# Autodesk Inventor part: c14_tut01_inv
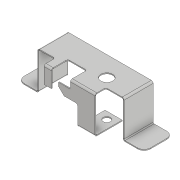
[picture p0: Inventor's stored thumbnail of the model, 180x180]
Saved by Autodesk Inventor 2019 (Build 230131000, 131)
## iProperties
Created: 2015-06
Part Number: c14_tut01_inv
Material: Generic
Document SubType Name: Sheet Metal
Designer: Sandeep
Density: 1 g/cm^3
Sheet Metal Rule: Default_mm
Appearance: Default
Flat Pattern Width: 11.1524 cm
Flat Pattern Length: 21.7129 cm
Flat Pattern Area: 242.15 cm^2
Sheet Metal Width: 111.524 mm
Sheet Metal Length: 217.129 mm
Sheet Metal Area: 24215.030 mm^2
Author: Sandeep
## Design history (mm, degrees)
node "Face1"
  sketch "Sketch1"
    geometry: L1 (0, 12)-(0, 44); L2 (0, 44)-(95, 44); L3 (95, 44)-(95, 12); L4 (95, 12)-(75, 12); L5 (75, 12)-(75, 0); L6 (75, 0)-(48, 0); L7 (48, 0)-(48, 18); L8 (48, 18)-(27, 18); L9 (27, 18)-(27, 0); L10 (27, 0)-(19, 0); L11 (19, 0)-(19, 12); L12 (19, 12)-(0, 12); L13 (0, 0)-(0, 88.508); L14 (0, 0)-(152.255, 0)
    constraints: 28 end point, 11 perpendicular, 4 point on line, 2 vertical, 1 horizontal
    dimensions: "d0" = 26 distance between parallel lines of L2 L8; "d1" = 19 distance between parallel lines of L13 L11; "d2" = 8 distance between parallel lines of L9 L11; "d3" = 32 distance between parallel lines of L12 L2; "d4" = 27 distance between parallel lines of L5 L7; "d5" = 20 distance between parallel lines of L3 L5; "d6" = 95 distance between parallel lines of L1 L3; "d7" = 44 distance between parallel lines of L6 L2
node "Contour Flange1"
node "Contour Flange3"
  sketch "Sketch10"
    geometry: L1 (0, 0)-(41, 0); L2 (41, 0)-(41, 30)
    constraints: 4 end point, 1 horizontal, 1 perpendicular
    dimensions: "d42" = 41 distance of L1.start L1.end; "d43" = 30 distance of L1.end L2.end
sketch "Sketch11"
  geometry: L1 (-3.447, 20)-(8, 20); L2 (8, 20)-(8, -8.777); L3 (8, -8.777)-(-3.447, -8.777); L4 (-3.447, -8.777)-(-3.447, 20); L5 (27, 37)-(27, 0) reference; L6 (0, 39)-(-21, 39) reference; 1 further point
  constraints: 8 end point, 2 parallel, 1 horizontal, 1 perpendicular
  dimensions: "d45" = 19 distance between parallel lines of L5 L2; "d104" = 19 distance between parallel lines of L6 L1
cut "Cut1" sketch "Sketch11" dims "d46" = 1 (= Thickness), "d47" = 0
node "Face2"
  sketch "Sketch12"
    geometry: L1 (0, -17)-(-13, -17); L2 (-13, -17)-(-13, -7); L3 (-13, -7)-(0, -7); L4 (0, 0)-(0, -17) reference; 1 further point
    constraints: 6 end point, 2 perpendicular, 1 horizontal, 1 point on line
    dimensions: "d54" = 13 distance between parallel lines of L2 L4; "d55" = 10 distance of L1.end L2.end
feature "Corner Round1" dims "d56" = 2
feature "Corner Chamfer1" dims "d57" = 6, "d58" = 6, angle "d59" = 45 deg
node "Flange1"
hole "Hole1" diameter "d72" = 13; stored, may be unused: countersink angle "d76" = 90 deg, drill point angle "d78" = 0 deg; dims "d70" = 9, "d71" = 22, "d73" = 6, "d74" = 4, "d75" = 2, "d77" = 1 (= Thickness)
hole "Hole2" diameter "d81" = 8; stored, may be unused: countersink angle "d85" = 90 deg, drill point angle "d87" = 0 deg; dims "d79" = 9, "d80" = 22, "d82" = 6, "d83" = 4, "d84" = 2, "d86" = 1 (= Thickness)
feature "Corner Round2" dims "d88" = 7
workplane "Work Plane1"
node "Contour Flange4"
  sketch "Sketch15"
    geometry: L1 (0, 0.919)-(0, -40.081); L2 (0, -40.081)-(-22, -40.081); 1 further point
    constraints: 4 end point, 1 perpendicular, 1 vertical
    dimensions: "d90" = 41 distance of L1.start L1.end; "d91" = 22 distance of L1.end L2.end
feature "Corner Round4" dims "d101" = 7
feature "Corner Round5" dims "d102" = 2
body "Solid1"
face "Plate1" dims "d103" = 1 (= Thickness)
sketch "Sketch6"
  geometry: L1 (-75, 1)-(20, 1) reference; L2 (20, 1)-(20, -39); L3 (20, -39)-(42, -39); L4 (-75, 1)-(-75, -39); L5 (-75, -39)-(-97, -39); 1 further point
  constraints: 8 end point, 2 perpendicular, 2 vertical
  dimensions: "d9" = 40 distance of L1.end L2.end; "d10" = 22 distance of L2.end L3.end; "d20" = 40 distance of L1.start L4.end
face "Plate2" dims "d11" = 1 (= BendReliefWidth), "d12" = 0.5 (= BendReliefDepth), "d13" = 2 (= MinimumRemnant), "d14" = 1 (= BendRadius), "d15" = 1 (= BendRadius), "d16" = 1, "d17" = 4 (= CornerReliefSize), "d18" = 1 (= GapSize), "d19" = 1 (= JacobiRadiusSize), "d103" = 1 (= Thickness), "SeamGap" = 0.01
bend "Bend1" dims "d11" = 1 (= BendReliefWidth), "d12" = 0.5 (= BendReliefDepth), "d13" = 2 (= MinimumRemnant), "d14" = 1 (= BendRadius), "d15" = 1 (= BendRadius), "d16" = 1, "d103" = 1 (= Thickness), "SeamGap" = 0.01
feature "Corner1" dims "d16" = 1, "d17" = 4 (= CornerReliefSize), "d18" = 1 (= GapSize), "d19" = 1 (= JacobiRadiusSize)
face "Plate4" dims "d33" = 1 (= BendReliefWidth), "d34" = 0.5 (= BendReliefDepth), "d35" = 2 (= MinimumRemnant), "d36" = 1 (= BendRadius), "d37" = 1 (= BendRadius), "d38" = 1, "d39" = 4 (= CornerReliefSize), "d40" = 1 (= GapSize), "d41" = 1 (= JacobiRadiusSize), "d103" = 1 (= Thickness), "SeamGap" = 0.01
bend "Bend3" dims "d33" = 1 (= BendReliefWidth), "d34" = 0.5 (= BendReliefDepth), "d35" = 2 (= MinimumRemnant), "d36" = 1 (= BendRadius), "d37" = 1 (= BendRadius), "d38" = 1, "d103" = 1 (= Thickness), "SeamGap" = 0.01
feature "Corner3" dims "d38" = 1, "d39" = 4 (= CornerReliefSize), "d40" = 1 (= GapSize), "d41" = 1 (= JacobiRadiusSize)
face "Plate5" dims "d49" = 1 (= BendRadius), "d50" = 1 (= BendReliefWidth), "d52" = 2 (= MinimumRemnant), "d103" = 1 (= Thickness)
bend "Bend4" dims "d49" = 1 (= BendRadius), "d50" = 1 (= BendReliefWidth), "d51" = 0.5 (= BendReliefDepth), "d52" = 2 (= MinimumRemnant), "d53" = 1 (= BendRadius), "d103" = 1 (= Thickness), "SeamGap" = 0.01
sketch "Sketch13"
  geometry: L1 through (-4, 0) direction (1, 6.84e-48); L2 through (0, 9.5) direction (-4.87e-32, 1); L3 (0, 19)-(-8, 19); L4 (-8, 19)-(-8, 0)
  constraints: 6 end point, 1 horizontal, 1 perpendicular, 1 vertical
face "Plate6" dims "d60" = 1 (= BendReliefWidth), "d61" = 0.5 (= BendReliefDepth), "d62" = 2 (= MinimumRemnant), "d63" = 1 (= BendRadius), "d64" = 19, "d65" = 90 deg, "d66" = 1 (= BendRadius), "d67" = 4 (= CornerReliefSize), "d68" = 1 (= GapSize), "d69" = 1 (= JacobiRadiusSize), "d103" = 1 (= Thickness), "SeamGap" = 0.01
bend "Bend5" dims "d60" = 1 (= BendReliefWidth), "d61" = 0.5 (= BendReliefDepth), "d62" = 2 (= MinimumRemnant), "d63" = 1 (= BendRadius), "d64" = 19, "d65" = 90 deg, "d66" = 1 (= BendRadius), "d103" = 1 (= Thickness), "SeamGap" = 0.01
feature "Corner4" dims "d64" = 19, "d65" = 90 deg, "d67" = 4 (= CornerReliefSize), "d68" = 1 (= GapSize), "d69" = 1 (= JacobiRadiusSize)
face "Plate7" dims "d92" = 1 (= BendReliefWidth), "d93" = 0.5 (= BendReliefDepth), "d94" = 2 (= MinimumRemnant), "d95" = 1 (= BendRadius), "d96" = 1 (= BendRadius), "d97" = 1, "d98" = 4 (= CornerReliefSize), "d99" = 1 (= GapSize), "d100" = 1 (= JacobiRadiusSize), "d103" = 1 (= Thickness), "SeamGap" = 0.01
bend "Bend6" dims "d92" = 1 (= BendReliefWidth), "d93" = 0.5 (= BendReliefDepth), "d94" = 2 (= MinimumRemnant), "d95" = 1 (= BendRadius), "d96" = 1 (= BendRadius), "d97" = 1, "d103" = 1 (= Thickness), "SeamGap" = 0.01
feature "Corner5" dims "d97" = 1, "d98" = 4 (= CornerReliefSize), "d99" = 1 (= GapSize), "d100" = 1 (= JacobiRadiusSize)
feature "Definition1"
other parameters: "Thickness" = 1 (derived), "BendRadius" = 1 (= Thickness), "BendReliefWidth" = 1 (= Thickness), "BendReliefDepth" = 0.5 (= 0.5 x Thickness), "CornerReliefSize" = 4 (= 4 x Thickness), "MinimumRemnant" = 2 (= 2 x Thickness), "TransitionRadius" = 1 (= BendRadius), "JacobiRadiusSize" = 1 (= BendRadius), "GapSize" = 1 (= Thickness), "d8" = 1 (= BendRadius), "BendRadius" = 1, "BendReliefDepth" = 0.5, "BendReliefWidth" = 1, "CornerReliefSize" = 4, "GapSize" = 1, "JacobiRadiusSize" = 1, "MinimumRemnant" = 2, "Thickness" = 1, "TransitionRadius" = 1
